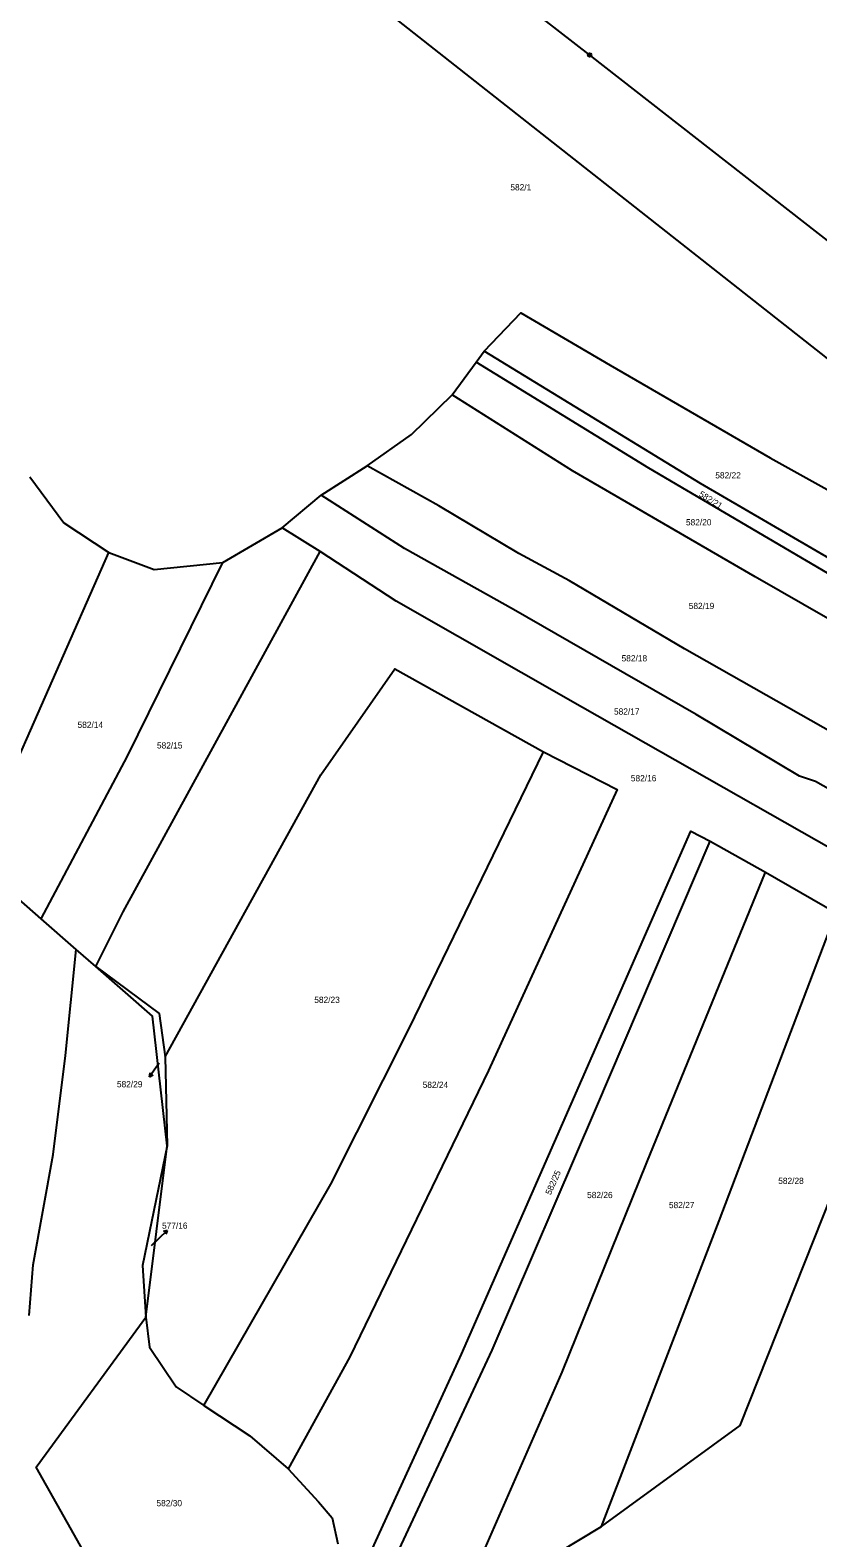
# Model space of a CAD drawing. Extents: x -757266 to -753360, y -1162585 to -1157740.
# Drawn here: x -756960.2 to -756745.7, y -1160596.2 to -1160185.6 of the extents above; entities that cross this region are included whole.
import ezdxf

# ---------------------------------------------------------------- set-up
doc = ezdxf.new("R2010")
doc.units = 0
for name, color, linetype in [('Hranice parcel', 7, 'Continuous'), ('Parcelní čísla', 7, 'Continuous'), ('Pop  PČ popisy', 7, 'Continuous'), ('Poz předměty', 7, 'Continuous')]:
    doc.layers.add(name, color=color, linetype=linetype)

msp = doc.modelspace()

# ---------------------------------------------------------------- linework, layer by layer
at = {"layer": 'Hranice parcel'}
for p, q in [((-756845.3, -1160284.87), (-756838.82, -1160275.99)), ((-756838.82, -1160275.99), (-756836.6, -1160273.01)), ((-756880.96, -1160312.2), (-756868.5, -1160304.23)), ((-756891.58, -1160321.1), (-756880.96, -1160312.2)), ((-756907.79, -1160330.58), (-756891.58, -1160321.1)), ((-756881.24, -1160327.57), (-756891.58, -1160321.1)), ((-756975.68, -1160411.5), (-756938.78, -1160327.85)), ((-756775.06, -1160406.46), (-756759.97, -1160414.94)), ((-756957.29, -1160427.57), (-756975.68, -1160411.5)), ((-756759.97, -1160414.94), (-756740.72, -1160425.98)), ((-756947.68, -1160435.98), (-756957.29, -1160427.57)), ((-756942.38, -1160440.62), (-756947.68, -1160435.98)), ((-756923.44, -1160465.23), (-756922.91, -1160489.44)), ((-756928.76, -1160536.05), (-756922.91, -1160489.44)), ((-756960.55, -1160535.6), (-756959.4, -1160521.88))]:
    msp.add_line(p, q, dxfattribs=at)
for points in [[(-756836.6, -1160273.01), (-756826.62, -1160262.6), (-756802.25, -1160276.82), (-756758.7, -1160302.02), (-756686.63, -1160342.06), (-756687.93, -1160345.95)], [(-756693.96, -1160361.99), (-756738.43, -1160336.23), (-756791.75, -1160304.88), (-756838.82, -1160275.99)], [(-756693.1, -1160359.12), (-756729.05, -1160337.36), (-756777.68, -1160309.08), (-756836.6, -1160273.01)], [(-756868.5, -1160304.23), (-756856.38, -1160295.7), (-756845.3, -1160284.87)], [(-756697.27, -1160372.06), (-756762.83, -1160334.49), (-756812.59, -1160305.56), (-756845.3, -1160284.87)], [(-756706.5, -1160396.92), (-756782.06, -1160354.11), (-756813.4, -1160335.52), (-756827.13, -1160328.09), (-756848.94, -1160315.16), (-756868.5, -1160304.23)], [(-756960.33, -1160307.23), (-756951.06, -1160319.74), (-756938.78, -1160327.85)], [(-756711.67, -1160409.79), (-756746.39, -1160390.2), (-756750.73, -1160388.75), (-756778.91, -1160372), (-756828.65, -1160343.34), (-756858.27, -1160326.75), (-756880.96, -1160312.2)], [(-756942.38, -1160440.62), (-756934.94, -1160425.71), (-756881.24, -1160327.57)], [(-756938.78, -1160327.85), (-756926.44, -1160332.44), (-756907.79, -1160330.58)], [(-756716.21, -1160423.27), (-756809.79, -1160370.08), (-756860.54, -1160341.13), (-756881.24, -1160327.57)], [(-756957.29, -1160427.57), (-756933.76, -1160383.28), (-756907.79, -1160330.58)], [(-756923.44, -1160465.23), (-756881.12, -1160388.4), (-756860.91, -1160359.48), (-756820.48, -1160382.16)], [(-756912.91, -1160560.16), (-756878.32, -1160499.9), (-756857, -1160457.5), (-756820.48, -1160382.16)], [(-756820.48, -1160382.16), (-756800.38, -1160392.4), (-756835.38, -1160468.87), (-756873.22, -1160546.91), (-756889.95, -1160577.39)], [(-756873.04, -1160612.16), (-756842.76, -1160546.18), (-756812.89, -1160478.08), (-756780.36, -1160403.72), (-756775.06, -1160406.46)], [(-756869.86, -1160620.94), (-756834.42, -1160545.08), (-756806.15, -1160479.34), (-756775.06, -1160406.46)], [(-756842.02, -1160612.11), (-756815.32, -1160551.09), (-756792.31, -1160494.01), (-756759.97, -1160414.94)], [(-756804.64, -1160593.12), (-756772.59, -1160509.87), (-756740.72, -1160425.98)], [(-756959.4, -1160521.88), (-756953.94, -1160491.8), (-756950.66, -1160464.82), (-756947.68, -1160435.98)], [(-756922.91, -1160489.44), (-756926.91, -1160454.14), (-756942.38, -1160440.62)], [(-756942.38, -1160440.62), (-756925.11, -1160453.38), (-756923.44, -1160465.23)], [(-756922.91, -1160489.44), (-756929.62, -1160522.04), (-756928.76, -1160536.05)], [(-756804.64, -1160593.12), (-756766.92, -1160565.61), (-756741.8, -1160502.52)], [(-756920.23, -1160616.61), (-756938.13, -1160613.33), (-756958.64, -1160576.94), (-756928.76, -1160536.05)], [(-756928.76, -1160536.05), (-756927.77, -1160544.29), (-756920.51, -1160555.1), (-756912.91, -1160560.16)], [(-756912.91, -1160560.16), (-756900.42, -1160568.44), (-756889.95, -1160577.39)], [(-756889.95, -1160577.39), (-756881.68, -1160586.35), (-756877.96, -1160590.74), (-756876.44, -1160597.83)], [(-756842.02, -1160612.11), (-756822.76, -1160603.95), (-756804.64, -1160593.12)]]:
    msp.add_lwpolyline(points, dxfattribs=at)
at = {"layer": 'Pop  PČ popisy'}
for p, q in [((-756925.99, -1160468.19), (-756927.711, -1160470.648)), ((-756927.711, -1160470.648), (-756927.547, -1160469.541)), ((-756925.11, -1160466.94), (-756925.99, -1160468.19)), ((-756927.711, -1160470.648), (-756926.727, -1160470.115)), ((-756927.17, -1160516.58), (-756925.07, -1160514.55)), ((-756925.07, -1160514.55), (-756922.911, -1160512.465)), ((-756922.911, -1160512.465), (-756923.98, -1160512.801)), ((-756922.911, -1160512.465), (-756923.284, -1160513.521))]:
    msp.add_line(p, q, dxfattribs=at)
at = {"layer": 'Poz předměty'}
for p, q in [((-756807.88, -1160192.32), (-756872.24, -1160142.38)), ((-756874.39, -1160171.69), (-756683.22, -1160322.27)), ((-756737.32, -1160247.42), (-756807.88, -1160192.32))]:
    msp.add_line(p, q, dxfattribs=at)
for radius in [0.5, 0.4, 0.3, 0.2, 0.1]:
    msp.add_circle((-756807.8834, -1160192.3199), radius, dxfattribs=at)

# ---------------------------------------------------------------- texts
at = {"layer": 'Parcelní čísla'}
for s, p in [('582/1', (-756829.47, -1160229.23)), ('582/22', (-756773.66, -1160307.67)), ('582/20', (-756781.65, -1160320.46)), ('582/19', (-756780.89, -1160343.25)), ('582/18', (-756799.18, -1160357.5)), ('582/17', (-756801.25, -1160372)), ('582/14', (-756947.34, -1160375.61)), ('582/15', (-756925.72, -1160381.22)), ('582/16', (-756796.66, -1160390.16)), ('582/23', (-756882.87, -1160450.51)), ('582/29', (-756936.615, -1160473.488)), ('582/24', (-756853.35, -1160473.65)), ('582/28', (-756756.52, -1160499.81)), ('582/26', (-756808.57, -1160503.67)), ('582/27', (-756786.29, -1160506.4)), ('577/16', (-756924.34, -1160512.02)), ('582/30', (-756925.84, -1160587.59))]:
    msp.add_text(s, height=1.7, dxfattribs=at).set_placement(p)
for s, rotation, p in [('582/21', 328, (-756778.29, -1160312.39)), ('582/25', 66, (-756818.473, -1160502.935))]:
    msp.add_text(s, height=1.7, rotation=rotation, dxfattribs=at).set_placement(p)

doc.saveas('drawing.dxf')
